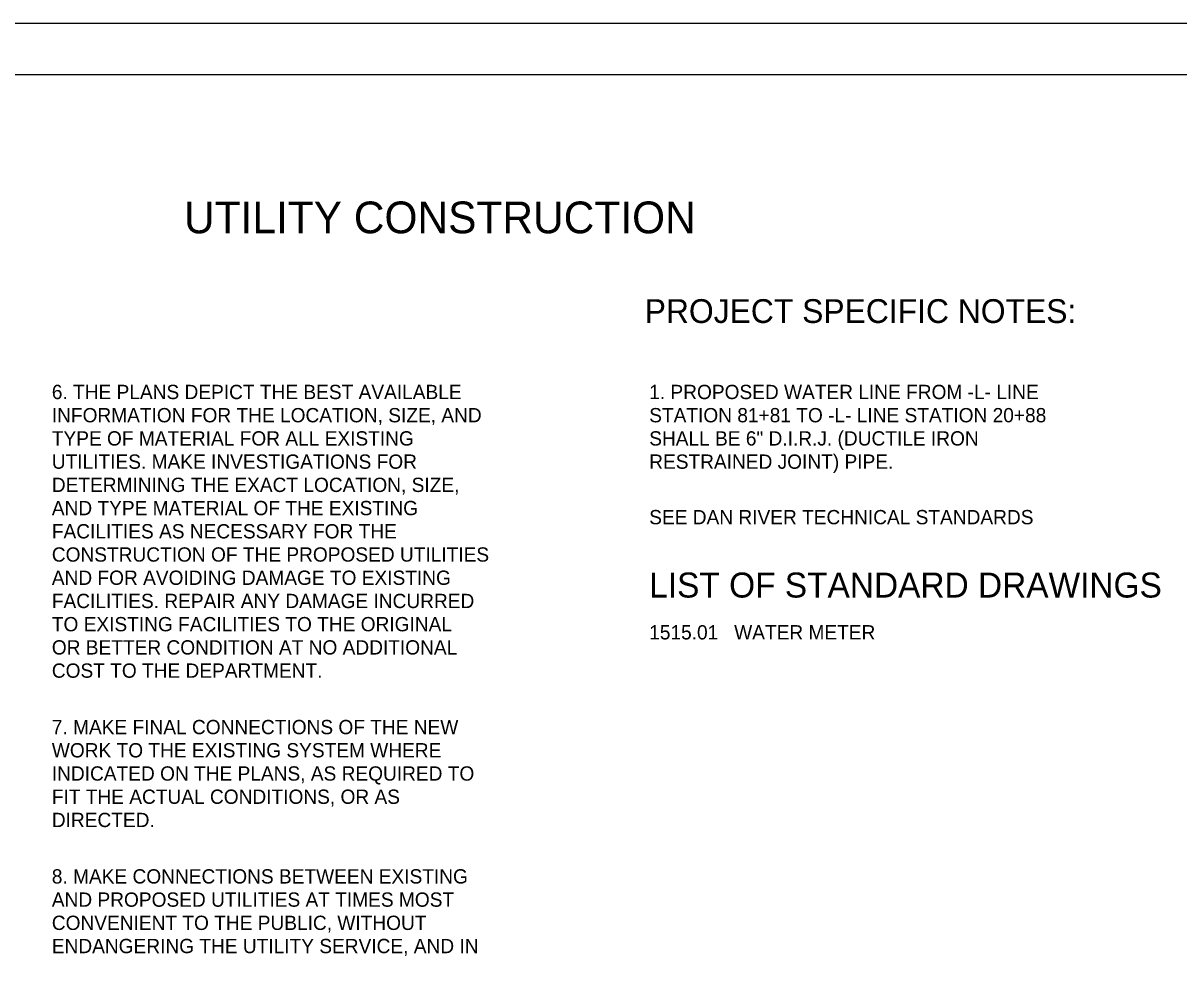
# Model space of a CAD drawing. Extents: x 2787886 to 2789612, y 1113277 to 1114394.
# Drawn here: x 2788498 to 2789192, y 1113832 to 1114394 of the extents above; entities that cross this region are included whole.
import ezdxf

# ---------------------------------------------------------------- set-up
doc = ezdxf.new("R2010")
doc.units = 0
doc.layers.add('Sheet_Plan_And_Profile_CELL', color=7, linetype='Continuous')
doc.layers.add('Sheet_Plot_Border_Outside_CELL', color=7, linetype='Continuous')

msp = doc.modelspace()

# ---------------------------------------------------------------- linework, layer by layer
at = {"layer": 'Sheet_Plan_And_Profile_CELL'}
msp.add_line((2789573.71, 1114363.23), (2787923.71, 1114363.23), dxfattribs=at)
at = {"layer": 'Sheet_Plot_Border_Outside_CELL'}
msp.add_lwpolyline([(2787885.62, 1114394.2), (2789611.78, 1114394.2), (2789611.78, 1113277.27), (2787885.62, 1113277.27)], close=True, dxfattribs=at)

# ---------------------------------------------------------------- texts
at = {"layer": 'Sheet_Plan_And_Profile_CELL'}
for s, height, p in [('UTILITY CONSTRUCTION', 19.0666, (2788594.19, 1114268.01)), ('PROJECT SPECIFIC NOTES:', 14.2999, (2788870.89, 1114214.15)), ('6. THE PLANS DEPICT THE BEST AVAILABLE ', 8.5799, (2788514.82, 1114168.45)), ('1. PROPOSED WATER LINE FROM -L- LINE ', 8.5799, (2788873.61, 1114168.45)), ('INFORMATION FOR THE LOCATION, SIZE, AND ', 8.5799, (2788514.82, 1114154.51)), ('STATION 81+81 TO -L- LINE STATION 20+88 ', 8.5799, (2788873.61, 1114154.51)), ('TYPE OF MATERIAL FOR ALL EXISTING ', 8.5799, (2788514.82, 1114140.57)), ('SHALL BE 6" D.I.R.J. (DUCTILE IRON ', 8.5799, (2788873.61, 1114140.57)), ('UTILITIES. MAKE INVESTIGATIONS FOR ', 8.5799, (2788514.82, 1114126.62)), ('RESTRAINED JOINT) PIPE.', 8.5799, (2788873.61, 1114126.62)), ('DETERMINING THE EXACT LOCATION, SIZE, ', 8.5799, (2788514.82, 1114112.68)), ('AND TYPE MATERIAL OF THE EXISTING ', 8.5799, (2788514.82, 1114098.74)), ('SEE DAN RIVER TECHNICAL STANDARDS', 8.5799, (2788873.61, 1114093.29)), ('FACILITIES AS NECESSARY FOR THE ', 8.5799, (2788514.82, 1114084.8)), ('CONSTRUCTION OF THE PROPOSED UTILITIES ', 8.5799, (2788514.82, 1114070.86)), ('AND FOR AVOIDING DAMAGE TO EXISTING ', 8.5799, (2788514.82, 1114056.91)), ('LIST OF STANDARD DRAWINGS', 15.0149, (2788873.61, 1114049.3)), ('FACILITIES. REPAIR ANY DAMAGE INCURRED ', 8.5799, (2788514.82, 1114042.97)), ('TO EXISTING FACILITIES TO THE ORIGINAL ', 8.5799, (2788514.82, 1114029.03)), ('1515.01   WATER METER', 8.5799, (2788873.61, 1114024.14)), ('OR BETTER CONDITION AT NO ADDITIONAL ', 8.5799, (2788514.82, 1114015.09)), ('COST TO THE DEPARTMENT.', 8.5799, (2788514.82, 1114001.14)), ('7. MAKE FINAL CONNECTIONS OF THE NEW ', 8.5799, (2788514.82, 1113967.25)), ('WORK TO THE EXISTING SYSTEM WHERE ', 8.5799, (2788514.82, 1113953.31)), ('INDICATED ON THE PLANS, AS REQUIRED TO ', 8.5799, (2788514.82, 1113939.37)), ('FIT THE ACTUAL CONDITIONS, OR AS ', 8.5799, (2788514.82, 1113925.43)), ('DIRECTED.', 8.58, (2788514.82, 1113911.48)), ('8. MAKE CONNECTIONS BETWEEN EXISTING ', 8.5799, (2788514.82, 1113877.6)), ('AND PROPOSED UTILITIES AT TIMES MOST ', 8.5799, (2788514.82, 1113863.65)), ('CONVENIENT TO THE PUBLIC, WITHOUT ', 8.5799, (2788514.82, 1113849.71)), ('ENDANGERING THE UTILITY SERVICE, AND IN ', 8.5799, (2788514.82, 1113835.77))]:
    msp.add_text(s, height=height, dxfattribs=at).set_placement(p)

doc.saveas('drawing.dxf')
